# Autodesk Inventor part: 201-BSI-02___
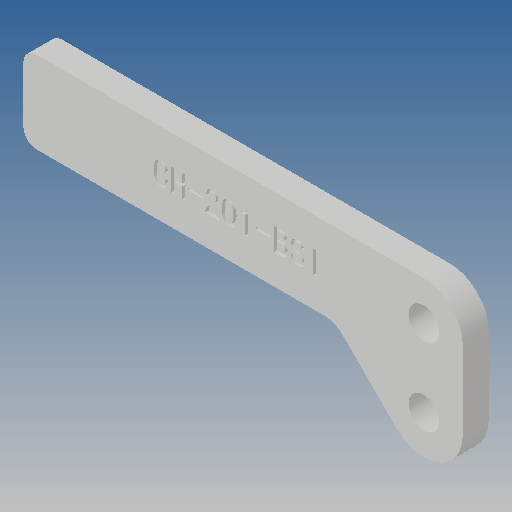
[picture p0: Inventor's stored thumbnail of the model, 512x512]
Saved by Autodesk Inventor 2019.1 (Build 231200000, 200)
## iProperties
Created: 2010-06
Part Number: 201-BSI-02___
Material: Ogólny
Document SubType Name: Modeling
Designer: CADENGINEERING4
Density: 1 g/cm^3
Appearance: Domyślna
Author: CADENGINEERING4
Revision Number: ANY
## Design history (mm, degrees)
feature "NONE"
node "Bryła1"
